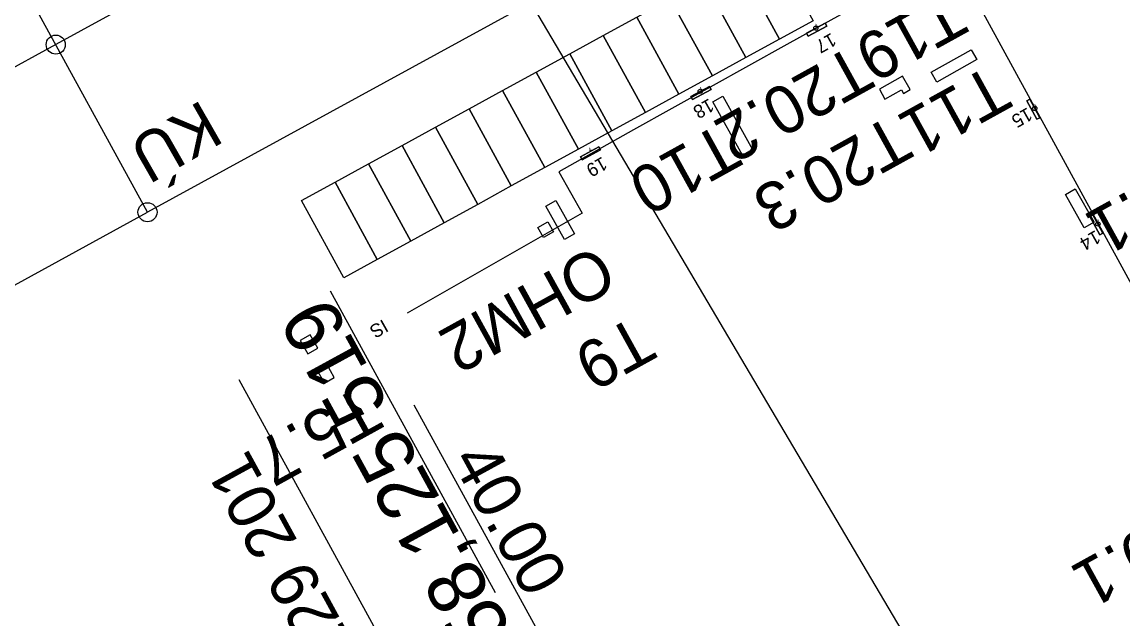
# Model space of a CAD drawing. Extents: x -783978 to -783565, y -1064821 to -1064596.
# Drawn here: x -783750.16 to -783721.35, y -1064699.59 to -1064683.97 of the extents above; entities that cross this region are included whole.
import ezdxf

# ---------------------------------------------------------------- set-up
doc = ezdxf.new("R2010")
doc.units = 0
for name, color, linetype in [('_PS_SO_číslo', 7, 'Continuous'), ('Default', 7, 'Continuous'), ('SO 01_10_01', 7, 'Continuous'), ('SO 01_12_01', 7, 'Continuous'), ('SO 01_50_01', 7, 'Continuous'), ('SO 01_77_01', 7, 'Continuous'), ('SO 01_86_04', 7, 'Continuous')]:
    doc.layers.add(name, color=color, linetype=linetype)

# ---------------------------------------------------------------- blocks, each defined once
blk = doc.blocks.new('POINT_DISPLAY')
at = {"layer": 'Default'}
blk.add_line((0, 0), (0, 0), dxfattribs=at)

msp = doc.modelspace()

# ---------------------------------------------------------------- linework, layer by layer
at = {"layer": '_PS_SO_číslo'}
msp.add_line((-783736.861, -1064683.435), (-783709.803, -1064729.26), dxfattribs=at)
at = {"layer": 'SO 01_10_01'}
for p, q in [((-783746.877, -1064688.946), (-783768.587, -1064649.261)), ((-783749.277, -1064684.559), (-783793.141, -1064708.557)), ((-783790.742, -1064712.943), (-783746.877, -1064688.946)), ((-783736.895, -1064707.191), (-783744.477, -1064693.332))]:
    msp.add_line(p, q, dxfattribs=at)
for points in [[(-783714.186, -1064665.36), (-783749.277, -1064684.559)], [(-783711.783, -1064669.747), (-783746.877, -1064688.946)]]:
    msp.add_lwpolyline(points, dxfattribs=at)
for centre in [(-783749.277, -1064684.559), (-783746.877, -1064688.946)]:
    msp.add_circle(centre, 0.25, dxfattribs=at)
at = {"layer": 'SO 01_12_01'}
msp.add_line((-783739.904, -1064693.985), (-783724.634, -1064721.897), dxfattribs=at)
for points in [[(-783729.461, -1064683.939), (-783730.338, -1064684.419), (-783731.442, -1064682.401), (-783730.565, -1064681.922), (-783729.461, -1064683.939)], [(-783730.338, -1064684.419), (-783731.216, -1064684.899), (-783732.32, -1064682.881), (-783731.442, -1064682.401), (-783730.338, -1064684.419)], [(-783731.216, -1064684.899), (-783732.093, -1064685.379), (-783733.197, -1064683.361), (-783732.32, -1064682.881), (-783731.216, -1064684.899)], [(-783732.093, -1064685.379), (-783732.97, -1064685.859), (-783734.074, -1064683.841), (-783733.197, -1064683.361), (-783732.093, -1064685.379)], [(-783732.97, -1064685.859), (-783733.848, -1064686.339), (-783734.952, -1064684.321), (-783734.074, -1064683.841), (-783732.97, -1064685.859)], [(-783733.848, -1064686.339), (-783734.725, -1064686.819), (-783735.829, -1064684.801), (-783734.952, -1064684.321), (-783733.848, -1064686.339)], [(-783734.725, -1064686.819), (-783735.602, -1064687.299), (-783736.706, -1064685.281), (-783735.829, -1064684.801), (-783734.725, -1064686.819)], [(-783735.602, -1064687.299), (-783736.479, -1064687.779), (-783737.583, -1064685.761), (-783736.706, -1064685.281), (-783735.602, -1064687.299)], [(-783736.479, -1064687.779), (-783737.357, -1064688.259), (-783738.461, -1064686.241), (-783737.583, -1064685.761), (-783736.479, -1064687.779)], [(-783737.357, -1064688.259), (-783738.234, -1064688.739), (-783739.338, -1064686.721), (-783738.461, -1064686.241), (-783737.357, -1064688.259)], [(-783738.234, -1064688.739), (-783739.111, -1064689.219), (-783740.215, -1064687.201), (-783739.338, -1064686.721), (-783738.234, -1064688.739)], [(-783739.111, -1064689.219), (-783739.989, -1064689.699), (-783741.093, -1064687.681), (-783740.215, -1064687.201), (-783739.111, -1064689.219)], [(-783739.989, -1064689.699), (-783740.866, -1064690.179), (-783741.97, -1064688.161), (-783741.093, -1064687.681), (-783739.989, -1064689.699)], [(-783740.866, -1064690.179), (-783741.743, -1064690.659), (-783742.847, -1064688.641), (-783741.97, -1064688.161), (-783740.866, -1064690.179)]]:
    msp.add_lwpolyline(points, dxfattribs=at)
at = {"layer": 'SO 01_50_01'}
msp.add_line((-783742.098, -1064691.001), (-783737.778, -1064698.897), dxfattribs=at)
at = {"layer": 'SO 01_77_01'}
for points in [[(-783726.37, -1064685.278), (-783725.324, -1064684.691), (-783725.177, -1064684.952), (-783726.223, -1064685.54)], [(-783726.92, -1064685.731), (-783727.116, -1064685.382), (-783727.726, -1064685.725), (-783727.579, -1064685.987), (-783727.143, -1064685.742), (-783727.09, -1064685.837)], [(-783731.826, -1064685.908), (-783731.042, -1064687.303), (-783731.304, -1064687.45), (-783732.087, -1064686.055)], [(-783722.598, -1064688.336), (-783722.108, -1064689.208), (-783722.369, -1064689.355), (-783722.859, -1064688.483)], [(-783736.195, -1064688.641), (-783735.706, -1064689.513), (-783735.967, -1064689.659), (-783736.457, -1064688.788)], [(-783736.66, -1064689.344), (-783736.398, -1064689.197), (-783736.251, -1064689.459), (-783736.513, -1064689.606)], [(-783742.682, -1064692.652), (-783742.421, -1064692.505), (-783742.617, -1064692.156), (-783742.878, -1064692.303)], [(-783742.249, -1064693.422), (-783741.988, -1064693.275), (-783742.184, -1064692.926), (-783742.445, -1064693.073)]]:
    msp.add_lwpolyline(points, close=True, dxfattribs=at)
at = {"layer": 'SO 01_86_04'}
for p, q in [((-783729.146, -1064683.995), (-783729.629, -1064684.259)), ((-783729.629, -1064684.259), (-783729.146, -1064683.995)), ((-783729.146, -1064683.995), (-783729.629, -1064684.259)), ((-783729.629, -1064684.259), (-783729.146, -1064683.995)), ((-783729.585, -1064684.338), (-783729.103, -1064684.074)), ((-783729.103, -1064684.074), (-783729.585, -1064684.338)), ((-783729.103, -1064684.074), (-783729.585, -1064684.338)), ((-783729.585, -1064684.338), (-783729.103, -1064684.074)), ((-783729.103, -1064684.074), (-783729.146, -1064683.995)), ((-783729.146, -1064683.995), (-783729.103, -1064684.074)), ((-783729.103, -1064684.074), (-783729.146, -1064683.995)), ((-783729.146, -1064683.995), (-783729.103, -1064684.074)), ((-783729.629, -1064684.259), (-783729.585, -1064684.338)), ((-783729.585, -1064684.338), (-783729.629, -1064684.259)), ((-783729.629, -1064684.259), (-783729.585, -1064684.338)), ((-783729.585, -1064684.338), (-783729.629, -1064684.259)), ((-783732.173, -1064685.651), (-783732.655, -1064685.915)), ((-783732.655, -1064685.915), (-783732.173, -1064685.651)), ((-783732.173, -1064685.651), (-783732.655, -1064685.915)), ((-783732.655, -1064685.915), (-783732.173, -1064685.651)), ((-783732.612, -1064685.994), (-783732.129, -1064685.73)), ((-783732.129, -1064685.73), (-783732.612, -1064685.994)), ((-783732.129, -1064685.73), (-783732.612, -1064685.994)), ((-783732.612, -1064685.994), (-783732.129, -1064685.73)), ((-783732.129, -1064685.73), (-783732.173, -1064685.651)), ((-783732.173, -1064685.651), (-783732.129, -1064685.73)), ((-783732.129, -1064685.73), (-783732.173, -1064685.651)), ((-783732.173, -1064685.651), (-783732.129, -1064685.73)), ((-783732.655, -1064685.915), (-783732.612, -1064685.994)), ((-783732.612, -1064685.994), (-783732.655, -1064685.915)), ((-783732.655, -1064685.915), (-783732.612, -1064685.994)), ((-783732.612, -1064685.994), (-783732.655, -1064685.915)), ((-783723.871, -1064686.032), (-783723.792, -1064685.989)), ((-783723.792, -1064685.989), (-783723.871, -1064686.032)), ((-783723.871, -1064686.032), (-783723.792, -1064685.989)), ((-783723.792, -1064685.989), (-783723.871, -1064686.032)), ((-783723.607, -1064686.514), (-783723.871, -1064686.032)), ((-783723.871, -1064686.032), (-783723.607, -1064686.514)), ((-783723.871, -1064686.032), (-783723.607, -1064686.514)), ((-783723.607, -1064686.514), (-783723.871, -1064686.032)), ((-783723.792, -1064685.989), (-783723.528, -1064686.471)), ((-783723.528, -1064686.471), (-783723.792, -1064685.989)), ((-783723.792, -1064685.989), (-783723.528, -1064686.471)), ((-783723.528, -1064686.471), (-783723.792, -1064685.989)), ((-783723.528, -1064686.471), (-783723.607, -1064686.514)), ((-783723.607, -1064686.514), (-783723.528, -1064686.471)), ((-783723.528, -1064686.471), (-783723.607, -1064686.514)), ((-783723.607, -1064686.514), (-783723.528, -1064686.471)), ((-783735.068, -1064687.235), (-783735.55, -1064687.499)), ((-783735.55, -1064687.499), (-783735.068, -1064687.235)), ((-783735.068, -1064687.235), (-783735.55, -1064687.499)), ((-783735.55, -1064687.499), (-783735.068, -1064687.235)), ((-783735.024, -1064687.314), (-783735.068, -1064687.235)), ((-783735.068, -1064687.235), (-783735.024, -1064687.314)), ((-783735.024, -1064687.314), (-783735.068, -1064687.235)), ((-783735.068, -1064687.235), (-783735.024, -1064687.314)), ((-783735.55, -1064687.499), (-783735.507, -1064687.578)), ((-783735.507, -1064687.578), (-783735.55, -1064687.499)), ((-783735.55, -1064687.499), (-783735.507, -1064687.578)), ((-783735.507, -1064687.578), (-783735.55, -1064687.499)), ((-783735.507, -1064687.578), (-783735.024, -1064687.314)), ((-783735.024, -1064687.314), (-783735.507, -1064687.578)), ((-783735.024, -1064687.314), (-783735.507, -1064687.578)), ((-783735.507, -1064687.578), (-783735.024, -1064687.314)), ((-783722.218, -1064689.054), (-783722.139, -1064689.01)), ((-783722.139, -1064689.01), (-783722.218, -1064689.054)), ((-783722.218, -1064689.054), (-783722.139, -1064689.01)), ((-783722.139, -1064689.01), (-783722.218, -1064689.054)), ((-783721.954, -1064689.536), (-783722.218, -1064689.054)), ((-783722.218, -1064689.054), (-783721.954, -1064689.536)), ((-783722.218, -1064689.054), (-783721.954, -1064689.536)), ((-783721.954, -1064689.536), (-783722.218, -1064689.054)), ((-783722.139, -1064689.01), (-783721.875, -1064689.493)), ((-783721.875, -1064689.493), (-783722.139, -1064689.01)), ((-783722.139, -1064689.01), (-783721.875, -1064689.493)), ((-783721.875, -1064689.493), (-783722.139, -1064689.01)), ((-783721.875, -1064689.493), (-783721.954, -1064689.536)), ((-783721.954, -1064689.536), (-783721.875, -1064689.493)), ((-783721.875, -1064689.493), (-783721.954, -1064689.536)), ((-783721.954, -1064689.536), (-783721.875, -1064689.493))]:
    msp.add_line(p, q, dxfattribs=at)
for points in [[(-783718.435, -1064695.445), (-783718.561, -1064695.519), (-783725.253, -1064683.277), (-783728.215, -1064677.831), (-783729.703, -1064675.111), (-783731.191, -1064672.392), (-783732.679, -1064669.672), (-783734.167, -1064666.953), (-783735.463, -1064664.584)], [(-783725.854, -1064682.172), (-783730.146, -1064684.558), (-783734.159, -1064686.788), (-783736.109, -1064687.89), (-783735.502, -1064688.966), (-783740.085, -1064691.591)]]:
    msp.add_lwpolyline(points, dxfattribs=at)
for centre in [(-783729.387, -1064684.127), (-783732.414, -1064685.783), (-783723.66, -1064686.23), (-783722.007, -1064689.252)]:
    msp.add_circle(centre, 0.0549, dxfattribs=at)

# ---------------------------------------------------------------- block references
at = {"layer": 'SO 01_86_04', "xscale": 0.010000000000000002, "yscale": 0.009999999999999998, "rotation": 28.683491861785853}
for p in [(-783729.146, -1064683.995), (-783729.146, -1064683.995), (-783729.103, -1064684.074), (-783729.103, -1064684.074), (-783729.629, -1064684.259), (-783729.629, -1064684.259), (-783729.585, -1064684.338), (-783729.585, -1064684.338), (-783729.344, -1064684.206), (-783732.173, -1064685.651), (-783732.173, -1064685.651), (-783732.129, -1064685.73), (-783732.129, -1064685.73), (-783732.655, -1064685.915), (-783732.655, -1064685.915), (-783732.612, -1064685.994), (-783732.612, -1064685.994), (-783732.371, -1064685.862), (-783723.871, -1064686.032), (-783723.871, -1064686.032), (-783723.792, -1064685.989), (-783723.792, -1064685.989), (-783723.739, -1064686.273), (-783723.607, -1064686.514), (-783723.607, -1064686.514), (-783723.528, -1064686.471), (-783723.528, -1064686.471), (-783735.068, -1064687.235), (-783735.068, -1064687.235), (-783735.55, -1064687.499), (-783735.55, -1064687.499), (-783735.266, -1064687.446), (-783735.024, -1064687.314), (-783735.024, -1064687.314), (-783735.507, -1064687.578), (-783735.507, -1064687.578), (-783722.218, -1064689.054), (-783722.218, -1064689.054), (-783722.139, -1064689.01), (-783722.139, -1064689.01), (-783722.086, -1064689.295), (-783721.954, -1064689.536), (-783721.954, -1064689.536), (-783721.875, -1064689.493), (-783721.875, -1064689.493)]:
    msp.add_blockref('POINT_DISPLAY', p, dxfattribs=at)

# ---------------------------------------------------------------- texts
at = {"layer": 'SO 01_10_01'}
for s, rotation, p in [('KÚ', 209.8143, (-783745.442, -1064685.987)), ('KÚ km 58,129 201', 118.6813, (-783737.627, -1064707.261))]:
    msp.add_text(s, height=1.25, rotation=rotation, dxfattribs=at).set_placement(p)
at = {"layer": 'SO 01_12_01'}
msp.add_text('konec úpravy nástupiště km 58,125 519', height=1.5, rotation=118.6813, dxfattribs=at).set_placement((-783725.126, -1064722.171))
at = {"layer": 'SO 01_50_01'}
msp.add_text('40.00', height=1.25, rotation=298.6835, dxfattribs=at).set_placement((-783738.945, -1064695.425))
at = {"layer": 'SO 01_77_01'}
for s, p in [('T19', (-783725.946, -1064683.094)), ('T20.2', (-783728.395, -1064684.535)), ('T11', (-783724.794, -1064685.054)), ('T20.3', (-783727.384, -1064686.365)), ('T10', (-783731.858, -1064686.579)), ('T8.1', (-783719.478, -1064687.413)), ('OHM2', (-783735.115, -1064689.779)), ('T9', (-783734.098, -1064691.622)), ('T5.7', (-783741.253, -1064693.446)), ('T20.1', (-783719.034, -1064696.187))]:
    msp.add_text(s, height=1.25, rotation=208.9107, dxfattribs=at).set_placement(p)
at = {"layer": 'SO 01_86_04'}
for s, height, rotation, p in [('4', 0.1, 28.6835, (-783729.387, -1064684.127)), ('17', 0.351, 209.46, (-783728.981, -1064684.239)), ('4', 0.1, 28.6835, (-783732.414, -1064685.783)), ('18', 0.351, 209.46, (-783732.179, -1064685.955)), ('6', 0.1, 28.6835, (-783723.66, -1064686.23)), ('15', 0.351, 209.46, (-783723.85, -1064686.192)), ('4', 0.1, 28.6835, (-783735.309, -1064687.367)), ('19', 0.351, 209.46, (-783734.976, -1064687.48)), ('2', 0.1, 28.6835, (-783722.007, -1064689.252)), ('14', 0.351, 209.46, (-783722.066, -1064689.402)), ('IS', 0.351, 209.46, (-783740.711, -1064691.737))]:
    msp.add_text(s, height=height, rotation=rotation, dxfattribs=at).set_placement(p)

doc.saveas('drawing.dxf')
